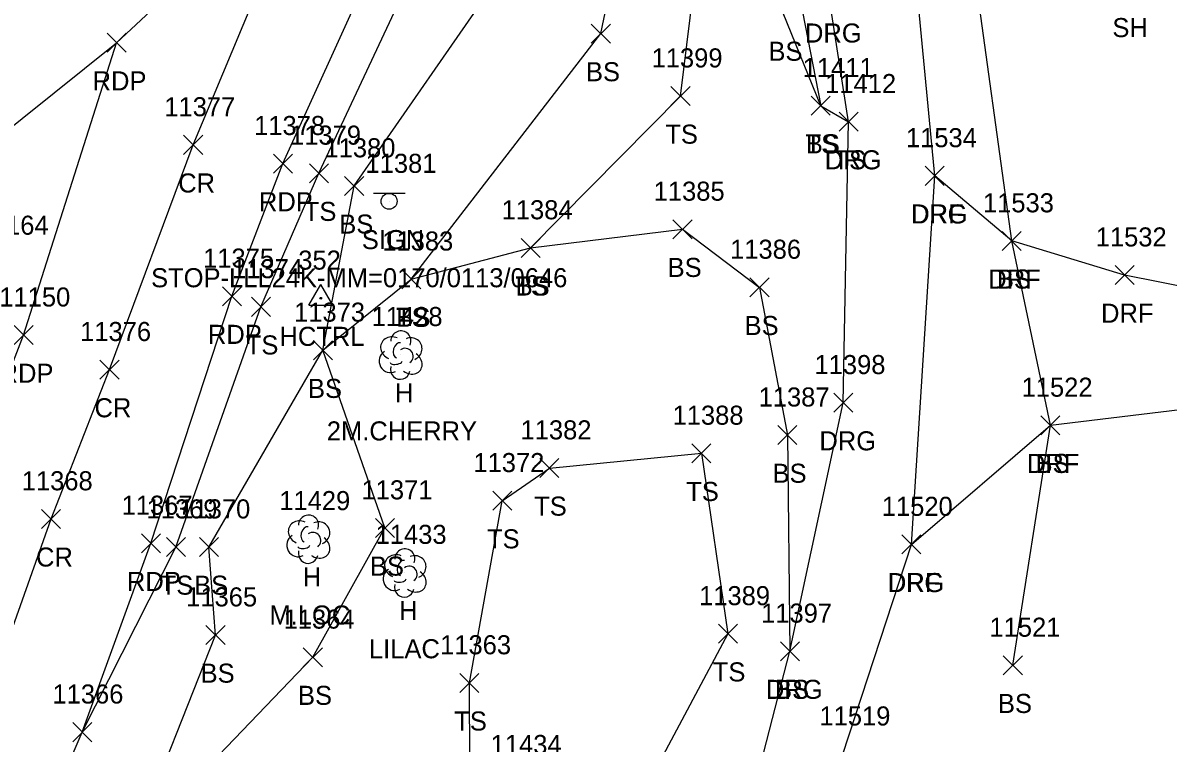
# Model space of a CAD drawing. Extents: x 1475671 to 1477951, y 592661 to 593821.
# Drawn here: x 1476858.4 to 1476978.4, y 593260.4 to 593335.9 of the extents above; entities that cross this region are included whole.
import ezdxf

# ---------------------------------------------------------------- set-up
doc = ezdxf.new("R2010")
doc.units = 0
for name, color, linetype in [('C_A', 7, 'Continuous'), ('C_I', 7, 'Continuous'), ('CPH', 7, 'Continuous'), ('L_A', 7, 'Continuous'), ('L_C', 7, 'Continuous'), ('L_I', 7, 'Continuous'), ('L_TIC', 7, 'Continuous'), ('LELB', 7, 'Continuous'), ('LTD', 7, 'Continuous'), ('P_A', 7, 'Continuous'), ('P_I', 7, 'Continuous'), ('P_TIC', 7, 'Continuous'), ('PET', 7, 'Continuous'), ('PRC', 7, 'Continuous'), ('R_A', 7, 'Continuous'), ('R_I', 7, 'Continuous'), ('R_TIC', 7, 'Continuous'), ('RDF', 7, 'Continuous'), ('RDG', 7, 'Continuous'), ('S_A', 7, 'Continuous'), ('S_C', 7, 'Continuous'), ('S_I', 7, 'Continuous'), ('SSGN', 7, 'Continuous')]:
    doc.layers.add(name, color=color, linetype=linetype)

msp = doc.modelspace()

# ---------------------------------------------------------------- linework, layer by layer
at = {"layer": 'CPH'}
for p, q in [((1476888.35, 593306.34), (1476889.6, 593308.51)), ((1476890.85, 593306.34), (1476889.6, 593308.51)), ((1476888.35, 593306.34), (1476890.85, 593306.34)), ((1476889.6, 593307.06), (1476889.6, 593307.06))]:
    msp.add_line(p, q, dxfattribs=at)
msp.add_circle((1476889.6, 593307.06), 0.0833, dxfattribs=at)
at = {"layer": 'L_TIC'}
for points in [[(1476917.96, 593333.82), (1476919.96, 593335.82)], [(1476919.96, 593333.82), (1476917.96, 593335.82)], [(1476926.31, 593327.27), (1476928.31, 593329.27)], [(1476928.31, 593327.27), (1476926.31, 593329.27)], [(1476941.01, 593326.25), (1476943.01, 593328.25)], [(1476943.01, 593326.25), (1476941.01, 593328.25)], [(1476941.01, 593326.25), (1476943.01, 593328.25)], [(1476943.01, 593326.25), (1476941.01, 593328.25)], [(1476943.94, 593324.58), (1476945.94, 593326.58)], [(1476945.94, 593324.58), (1476943.94, 593326.58)], [(1476888.41, 593319.17), (1476890.41, 593321.17)], [(1476890.41, 593319.17), (1476888.41, 593321.17)], [(1476892.1, 593317.84), (1476894.1, 593319.84)], [(1476894.1, 593317.84), (1476892.1, 593319.84)], [(1476926.52, 593313.29), (1476928.52, 593315.29)], [(1476928.52, 593313.29), (1476926.52, 593315.29)], [(1476961.04, 593312.07), (1476963.04, 593314.07)], [(1476963.04, 593312.07), (1476961.04, 593314.07)], [(1476910.59, 593311.34), (1476912.59, 593313.34)], [(1476912.59, 593311.34), (1476910.59, 593313.34)], [(1476910.59, 593311.34), (1476912.59, 593313.34)], [(1476912.59, 593311.34), (1476910.59, 593313.34)], [(1476898.08, 593308.06), (1476900.08, 593310.06)], [(1476900.08, 593308.06), (1476898.08, 593310.06)], [(1476898.08, 593308.06), (1476900.08, 593310.06)], [(1476900.08, 593308.06), (1476898.08, 593310.06)], [(1476934.59, 593307.2), (1476936.59, 593309.2)], [(1476936.59, 593307.2), (1476934.59, 593309.2)], [(1476882.33, 593305.16), (1476884.33, 593307.16)], [(1476884.33, 593305.16), (1476882.33, 593307.16)], [(1476888.82, 593300.6), (1476890.82, 593302.6)], [(1476890.82, 593300.6), (1476888.82, 593302.6)], [(1476888.82, 593300.6), (1476890.82, 593302.6)], [(1476890.82, 593300.6), (1476888.82, 593302.6)], [(1476965.09, 593292.73), (1476967.09, 593294.73)], [(1476967.09, 593292.73), (1476965.09, 593294.73)], [(1476937.52, 593291.7), (1476939.52, 593293.7)], [(1476939.52, 593291.7), (1476937.52, 593293.7)], [(1476928.5, 593289.79), (1476930.5, 593291.79)], [(1476930.5, 593289.79), (1476928.5, 593291.79)], [(1476912.56, 593288.25), (1476914.56, 593290.25)], [(1476914.56, 593288.25), (1476912.56, 593290.25)], [(1476912.56, 593288.25), (1476914.56, 593290.25)], [(1476914.56, 593288.25), (1476912.56, 593290.25)], [(1476907.62, 593284.82), (1476909.62, 593286.82)], [(1476909.62, 593284.82), (1476907.62, 593286.82)], [(1476895.32, 593281.96), (1476897.32, 593283.96)], [(1476897.32, 593281.96), (1476895.32, 593283.96)], [(1476873.41, 593279.96), (1476875.41, 593281.96)], [(1476875.41, 593279.96), (1476873.41, 593281.96)], [(1476876.88, 593279.96), (1476878.88, 593281.96)], [(1476878.88, 593279.96), (1476876.88, 593281.96)], [(1476877.56, 593270.73), (1476879.56, 593272.73)], [(1476879.56, 593270.73), (1476877.56, 593272.73)], [(1476931.29, 593270.86), (1476933.29, 593272.86)], [(1476933.29, 593270.86), (1476931.29, 593272.86)], [(1476887.77, 593268.4), (1476889.77, 593270.4)], [(1476889.77, 593268.4), (1476887.77, 593270.4)], [(1476937.78, 593269.03), (1476939.78, 593271.03)], [(1476939.78, 593269.03), (1476937.78, 593271.03)], [(1476961.15, 593267.55), (1476963.15, 593269.55)], [(1476963.15, 593267.55), (1476961.15, 593269.55)], [(1476904.18, 593265.71), (1476906.18, 593267.71)], [(1476906.18, 593265.71), (1476904.18, 593267.71)], [(1476863.6, 593260.54), (1476865.6, 593262.54)], [(1476865.6, 593260.54), (1476863.6, 593262.54)]]:
    msp.add_lwpolyline(points, dxfattribs=at)
at = {"layer": 'LELB'}
for points in [[(1476962.15, 593268.55), (1476966.09, 593293.73), (1476962.04, 593313.07), (1476957.94, 593342.76), (1476956.85, 593364.92), (1476946.71, 593381.5), (1476947.26, 593385.01), (1476945.57, 593387.27), (1476956.77, 593393.64), (1476963.43, 593396.59), (1476970.91, 593403.07), (1476974.88, 593411.06), (1477002.6, 593437.22), (1477013.99, 593445.85), (1477022.63, 593453.15), (1477030.46, 593458.56)], [(1476864.6, 593261.54), (1476874.41, 593280.96), (1476883.33, 593306.16), (1476889.41, 593320.17), (1476901.29, 593345.55), (1476912.71, 593361.1), (1476913.88, 593366.51), (1476917.83, 593370.13), (1476924.18, 593369.9), (1476931.14, 593361.7), (1476938.47, 593345.55), (1476942.01, 593327.25), (1476944.94, 593325.58)], [(1476844.89, 593161.77), (1476849.57, 593180.8), (1476849.13, 593190.54), (1476855.62, 593209.87), (1476862.35, 593222.47), (1476869.87, 593249.68), (1476878.56, 593271.73), (1476877.88, 593280.96), (1476889.82, 593301.6), (1476893.1, 593318.84), (1476908.59, 593341.2), (1476918.55, 593355.38), (1476919.84, 593361.76), (1476917.93, 593365.87), (1476921.61, 593367.66), (1476922.08, 593366.69), (1476922.63, 593360.35), (1476925.59, 593366.62)], [(1476899.08, 593309.06), (1476911.59, 593312.34), (1476927.31, 593328.27), (1476930.66, 593355.51), (1476925.59, 593366.62)], [(1476882.63, 593203.65), (1476875.74, 593222.23), (1476869.87, 593249.68), (1476888.77, 593269.4), (1476896.32, 593282.96), (1476889.82, 593301.6), (1476899.08, 593309.06), (1476918.96, 593334.82), (1476923.19, 593355.07), (1476922.63, 593360.35)], [(1476942.01, 593327.25), (1476938.09, 593336.97), (1476930.66, 593355.51)], [(1476911.59, 593312.34), (1476927.52, 593314.29), (1476935.59, 593308.2), (1476938.52, 593292.7), (1476938.78, 593270.03)], [(1476913.56, 593289.25), (1476929.5, 593290.79), (1476932.29, 593271.86), (1476922.08, 593252.68), (1476914.39, 593239.23), (1476908.84, 593217.58), (1476908.1, 593203.87)], [(1476898.32, 593201.52), (1476892.94, 593222.33), (1476905.3, 593240.8), (1476905.18, 593266.71), (1476908.62, 593285.82), (1476913.56, 593289.25)]]:
    msp.add_lwpolyline(points, dxfattribs=at)
at = {"layer": 'LTD'}
for p, q in [((1476897.95, 593301.14), (1476897.95, 593301.14)), ((1476897.95, 593301.14), (1476897.95, 593301.14)), ((1476888.28, 593281.83), (1476888.28, 593281.83)), ((1476888.28, 593281.83), (1476888.28, 593281.83)), ((1476898.37, 593278.29), (1476898.37, 593278.29)), ((1476898.37, 593278.29), (1476898.37, 593278.29))]:
    msp.add_line(p, q, dxfattribs=at)
for centre in [(1476898, 593302.58), (1476888.32, 593283.26), (1476898.42, 593279.72)]:
    msp.add_arc(centre, 1.05, 335.5272, 180.9563, dxfattribs=at)
for centre, major_axis, ratio, start_param, end_param in [((1476897.16, 593301.81), (1.21, -0.51), 0.895232, 1.570796, 4.712389), ((1476898.99, 593301.73), (-1.14, -0.48), 0.949671, 1.570796, 4.712389), ((1476896.87, 593300.43), (0.58, -1.04), 0.959034, 3.141593, 6.283185), ((1476897.74, 593301.6), (-0.208, -0.792), 0.645439, 3.141593, 6.283185), ((1476898.45, 593300.98), (-0.5, 0.667), 0.989748, 3.141593, 6.283185), ((1476897.49, 593300.39), (-0.625, -0.083), 0.423636, 0, 3.141593), ((1476898.95, 593300.31), (-1.09, 0.79), 0.841452, 1.570796, 4.712389), ((1476897.95, 593299.64), (0.26, 1.06), 0.942809, 1.570796, 4.712389), ((1476887.49, 593282.5), (1.21, -0.51), 0.895232, 1.570796, 4.712389), ((1476889.32, 593282.41), (-1.14, -0.48), 0.949671, 1.570796, 4.712389), ((1476888.07, 593282.29), (-0.208, -0.792), 0.645439, 3.141593, 6.283185), ((1476888.78, 593281.66), (-0.5, 0.667), 0.989748, 3.141593, 6.283185), ((1476887.19, 593281.12), (0.58, -1.04), 0.959034, 3.141593, 6.283185), ((1476887.82, 593281.08), (-0.625, -0.083), 0.423636, 0, 3.141593), ((1476889.28, 593281), (-1.09, 0.79), 0.841452, 1.570796, 4.712389), ((1476888.28, 593280.33), (0.26, 1.06), 0.942809, 1.570796, 4.712389), ((1476897.58, 593278.95), (1.21, -0.51), 0.895232, 1.570796, 4.712389), ((1476899.41, 593278.87), (-1.14, -0.48), 0.949671, 1.570796, 4.712389), ((1476898.16, 593278.75), (-0.208, -0.792), 0.645439, 3.141593, 6.283185), ((1476898.87, 593278.12), (-0.5, 0.667), 0.989748, 3.141593, 6.283185), ((1476897.29, 593277.58), (0.58, -1.04), 0.959034, 3.141593, 6.283185), ((1476897.92, 593277.54), (-0.625, -0.083), 0.423636, 0, 3.141593), ((1476899.37, 593277.45), (-1.09, 0.79), 0.841452, 1.570796, 4.712389), ((1476898.37, 593276.79), (0.26, 1.06), 0.942809, 1.570796, 4.712389)]:
    msp.add_ellipse(centre, major_axis=major_axis, ratio=ratio, start_param=start_param, end_param=end_param, dxfattribs=at)
at = {"layer": 'P_TIC'}
for points in [[(1476867.19, 593332.86), (1476869.19, 593334.86)], [(1476869.19, 593332.86), (1476867.19, 593334.86)], [(1476867.19, 593332.86), (1476869.19, 593334.86)], [(1476869.19, 593332.86), (1476867.19, 593334.86)], [(1476875.22, 593322.15), (1476877.22, 593324.15)], [(1476877.22, 593322.15), (1476875.22, 593324.15)], [(1476884.63, 593320.18), (1476886.63, 593322.18)], [(1476886.63, 593320.18), (1476884.63, 593322.18)], [(1476879.28, 593306.27), (1476881.28, 593308.27)], [(1476881.28, 593306.27), (1476879.28, 593308.27)], [(1476857.44, 593302.19), (1476859.44, 593304.19)], [(1476859.44, 593302.19), (1476857.44, 593304.19)], [(1476866.45, 593298.57), (1476868.45, 593300.57)], [(1476868.45, 593298.57), (1476866.45, 593300.57)], [(1476860.32, 593282.91), (1476862.32, 593284.91)], [(1476862.32, 593282.91), (1476860.32, 593284.91)], [(1476870.79, 593280.35), (1476872.79, 593282.35)], [(1476872.79, 593280.35), (1476870.79, 593282.35)], [(1476863.6, 593260.54), (1476865.6, 593262.54)], [(1476865.6, 593260.54), (1476863.6, 593262.54)]]:
    msp.add_lwpolyline(points, dxfattribs=at)
at = {"layer": 'PET'}
for points in [[(1476493.61, 593061.9), (1476518.9, 593073.26), (1476550.12, 593088.22), (1476579.1, 593105.35), (1476612.57, 593127.79), (1476627.64, 593138.01), (1476653.65, 593155.86), (1476677.37, 593174.62), (1476705.43, 593196.67), (1476722.66, 593210.69), (1476749.61, 593233.45), (1476768.81, 593249.96), (1476797.5, 593274.02), (1476824.82, 593297.55), (1476845, 593315.29), (1476868.19, 593333.86), (1476888.66, 593352.98), (1476918.01, 593376.95), (1476944.23, 593398.87), (1476967.73, 593418.7), (1476998.53, 593444.47)], [(1476852.05, 593085.53), (1476845.73, 593108.15), (1476841.01, 593134.78), (1476840.06, 593162.08), (1476843.4, 593187.72), (1476850.39, 593217.62), (1476860.98, 593253.11), (1476864.6, 593261.54), (1476871.79, 593281.35), (1476880.28, 593307.27), (1476885.63, 593321.18), (1476897.83, 593348.03), (1476918.01, 593376.95)], [(1476550.12, 593088.22), (1476546.99, 593080.79), (1476546.62, 593074.3), (1476558.02, 593070.45), (1476566.6, 593070.83), (1476605.7, 593074.02), (1476651.65, 593078.89), (1476683.81, 593086.28), (1476716.78, 593091.72), (1476756.3, 593096.32), (1476786.76, 593094.61), (1476795.52, 593092.66), (1476816.88, 593085.29), (1476835.43, 593074.22), (1476828.62, 593102.02), (1476824.42, 593119.75), (1476821.59, 593140.77), (1476821.02, 593163.56), (1476821.92, 593180.44), (1476827.12, 593207.84), (1476837.47, 593243.39), (1476848.83, 593278.3), (1476858.44, 593303.19), (1476868.19, 593333.86)]]:
    msp.add_lwpolyline(points, dxfattribs=at)
at = {"layer": 'PRC'}
msp.add_lwpolyline([(1476853.41, 593046.52), (1476841.6, 593084.28), (1476835.78, 593107.15), (1476831.7, 593132.51), (1476830.84, 593162.78), (1476833.45, 593190.92), (1476841.31, 593223.69), (1476851.49, 593256.16), (1476861.32, 593283.91), (1476867.45, 593299.57), (1476876.22, 593323.15), (1476888.66, 593352.98)], dxfattribs=at)
at = {"layer": 'R_TIC'}
for points in [[(1476943.94, 593324.58), (1476945.94, 593326.58)], [(1476945.94, 593324.58), (1476943.94, 593326.58)], [(1476952.96, 593318.9), (1476954.96, 593320.9)], [(1476954.96, 593318.9), (1476952.96, 593320.9)], [(1476952.96, 593318.9), (1476954.96, 593320.9)], [(1476954.96, 593318.9), (1476952.96, 593320.9)], [(1476961.04, 593312.07), (1476963.04, 593314.07)], [(1476963.04, 593312.07), (1476961.04, 593314.07)], [(1476972.87, 593308.49), (1476974.87, 593310.49)], [(1476974.87, 593308.49), (1476972.87, 593310.49)], [(1476943.38, 593295.1), (1476945.38, 593297.1)], [(1476945.38, 593295.1), (1476943.38, 593297.1)], [(1476965.09, 593292.73), (1476967.09, 593294.73)], [(1476967.09, 593292.73), (1476965.09, 593294.73)], [(1476950.52, 593280.23), (1476952.52, 593282.23)], [(1476952.52, 593280.23), (1476950.52, 593282.23)], [(1476950.52, 593280.23), (1476952.52, 593282.23)], [(1476952.52, 593280.23), (1476950.52, 593282.23)], [(1476937.78, 593269.03), (1476939.78, 593271.03)], [(1476939.78, 593269.03), (1476937.78, 593271.03)]]:
    msp.add_lwpolyline(points, dxfattribs=at)
at = {"layer": 'RDF'}
for points in [[(1477025, 593308.34), (1477007.8, 593304.64), (1476992.38, 593305.8), (1476973.87, 593309.49), (1476962.04, 593313.07), (1476953.96, 593319.9)], [(1476951.52, 593281.23), (1476966.09, 593293.73), (1476987.21, 593296.29), (1477002.39, 593292.57), (1477022.95, 593291.85)]]:
    msp.add_lwpolyline(points, dxfattribs=at)
at = {"layer": 'RDG'}
for points in [[(1476954.02, 593202.34), (1476939.16, 593211.9), (1476944.34, 593259.24), (1476951.52, 593281.23), (1476953.96, 593319.9), (1476951.87, 593341.86), (1476947.54, 593363.24), (1476941.61, 593379.55), (1476939.44, 593381.51), (1476939.12, 593387.06), (1476944.23, 593398.87)], [(1476850.39, 593217.62), (1476855.62, 593209.87), (1476871.37, 593205.7), (1476882.63, 593203.65), (1476898.32, 593201.52), (1476908.1, 593203.87), (1476921.63, 593214.39), (1476929.61, 593231.45), (1476934.18, 593252.23), (1476938.78, 593270.03), (1476944.38, 593296.1), (1476944.94, 593325.58), (1476942.87, 593338.88), (1476933.5, 593367.74), (1476927.3, 593373.86), (1476918.01, 593376.95)]]:
    msp.add_lwpolyline(points, dxfattribs=at)
at = {"layer": 'SSGN'}
for p, q in [((1476895.11, 593318.07), (1476898.45, 593318.07)), ((1476896.76, 593317.23), (1476896.76, 593317.23))]:
    msp.add_line(p, q, dxfattribs=at)
msp.add_circle((1476896.76, 593317.23), 0.833, dxfattribs=at)

# ---------------------------------------------------------------- texts
at = {"layer": 'C_A'}
msp.add_text('HCTRL', height=2, dxfattribs=at).set_placement((1476885.27, 593302.06))
at = {"layer": 'C_I'}
msp.add_text('352', height=2, dxfattribs=at).set_placement((1476887.24, 593310.06))
at = {"layer": 'L_A'}
for s, p in [('SH', (1476972.59, 593334.45)), ('BS', (1476936.53, 593331.97)), ('BS', (1476917.4, 593329.82)), ('TS', (1476925.72, 593323.27)), ('TS', (1476940.42, 593322.25)), ('BS', (1476940.45, 593322.25)), ('TS', (1476943.35, 593320.58)), ('TS', (1476887.82, 593315.17)), ('BS', (1476891.54, 593313.84)), ('BS', (1476925.96, 593309.29)), ('BS', (1476960.48, 593308.07)), ('TS', (1476909.99, 593307.34)), ('BS', (1476910.03, 593307.34)), ('TS', (1476897.49, 593304.06)), ('BS', (1476897.52, 593304.06)), ('BS', (1476934.03, 593303.2)), ('TS', (1476881.74, 593301.16)), ('BS', (1476888.26, 593296.6)), ('BS', (1476888.26, 593296.6)), ('H', (1476897.38, 593296.14)), ('BS', (1476964.53, 593288.73)), ('BS', (1476936.96, 593287.7)), ('TS', (1476927.91, 593285.79)), ('TS', (1476911.97, 593284.25)), ('TS', (1476911.97, 593284.25)), ('TS', (1476907.03, 593280.82)), ('BS', (1476894.76, 593277.96)), ('H', (1476887.71, 593276.83)), ('TS', (1476872.82, 593275.96)), ('BS', (1476876.32, 593275.96)), ('H', (1476897.81, 593273.29)), ('BS', (1476877, 593266.73)), ('TS', (1476930.7, 593266.86)), ('BS', (1476937.22, 593265.03)), ('BS', (1476887.21, 593264.4)), ('BS', (1476960.59, 593263.55)), ('TS', (1476903.59, 593261.71))]:
    msp.add_text(s, height=2, dxfattribs=at).set_placement(p)
at = {"layer": 'L_C'}
for s, p in [('2M.CHERRY', (1476890.23, 593292.14)), ('M.LOC', (1476884.22, 593272.83)), ('LILAC', (1476894.65, 593269.29))]:
    msp.add_text(s, height=2, dxfattribs=at).set_placement(p)
at = {"layer": 'L_I'}
for s, p in [('11399', (1476924.28, 593331.27)), ('11411', (1476940.12, 593330.25)), ('11411', (1476940.12, 593330.25)), ('11412', (1476942.48, 593328.58)), ('11379', (1476886.38, 593323.17)), ('11380', (1476889.99, 593321.84)), ('11385', (1476924.5, 593317.29)), ('11384', (1476908.56, 593315.34)), ('11384', (1476908.56, 593315.34)), ('11533', (1476959.02, 593316.07)), ('11164', (1476853.63, 593313.72)), ('11164', (1476853.63, 593313.72)), ('11383', (1476896.05, 593312.06)), ('11383', (1476896.05, 593312.06)), ('11386', (1476932.51, 593311.2)), ('11374', (1476880.3, 593309.16)), ('11373', (1476886.8, 593304.6)), ('11373', (1476886.8, 593304.6)), ('11428', (1476894.93, 593304.14)), ('11522', (1476963.07, 593296.73)), ('11387', (1476935.5, 593295.7)), ('11388', (1476926.48, 593293.79)), ('11382', (1476910.54, 593292.25)), ('11382', (1476910.54, 593292.25)), ('11372', (1476905.6, 593288.82)), ('11371', (1476893.87, 593285.96)), ('11369', (1476871.33, 593283.96)), ('11370', (1476874.77, 593283.96)), ('11429', (1476885.25, 593284.83)), ('11433', (1476895.35, 593281.29)), ('11365', (1476875.49, 593274.73)), ('11389', (1476929.26, 593274.86)), ('11397', (1476935.76, 593273.03)), ('11364', (1476885.7, 593272.4)), ('11521', (1476959.7, 593271.55)), ('11363', (1476902.11, 593269.71)), ('11366', (1476861.47, 593264.54)), ('11434', (1476907.41, 593259.25))]:
    msp.add_text(s, height=2, dxfattribs=at).set_placement(p)
at = {"layer": 'P_A'}
for s, p in [('RDP', (1476865.68, 593328.86)), ('RDP', (1476865.68, 593328.86)), ('CR', (1476874.65, 593318.15)), ('RDP', (1476883.12, 593316.18)), ('RDP', (1476877.77, 593302.27)), ('RDP', (1476855.93, 593298.19)), ('CR', (1476865.88, 593294.57)), ('CR', (1476859.75, 593278.91)), ('RDP', (1476869.28, 593276.35))]:
    msp.add_text(s, height=2, dxfattribs=at).set_placement(p)
at = {"layer": 'P_I'}
for s, p in [('11377', (1476873.2, 593326.15)), ('11378', (1476882.61, 593324.18)), ('11375', (1476877.26, 593310.27)), ('11150', (1476855.9, 593306.19)), ('11376', (1476864.37, 593302.57)), ('11368', (1476858.25, 593286.91)), ('11367', (1476868.72, 593284.35)), ('11366', (1476861.47, 593264.54))]:
    msp.add_text(s, height=2, dxfattribs=at).set_placement(p)
at = {"layer": 'R_A'}
for s, p in [('DRG', (1476940.36, 593333.88)), ('DRG', (1476942.43, 593320.58)), ('DRG', (1476951.45, 593314.9)), ('DRF', (1476951.5, 593314.9)), ('DRF', (1476959.58, 593308.07)), ('DRF', (1476971.4, 593304.49)), ('DRG', (1476941.87, 593291.1)), ('DRF', (1476963.63, 593288.73)), ('DRG', (1476949.01, 593276.23)), ('DRF', (1476949.06, 593276.23)), ('DRG', (1476936.27, 593265.03))]:
    msp.add_text(s, height=2, dxfattribs=at).set_placement(p)
at = {"layer": 'R_I'}
for s, p in [('11412', (1476942.48, 593328.58)), ('11534', (1476950.94, 593322.9)), ('11534', (1476950.94, 593322.9)), ('11533', (1476959.02, 593316.07)), ('11532', (1476970.84, 593312.49)), ('11398', (1476941.36, 593299.1)), ('11522', (1476963.07, 593296.73)), ('11520', (1476948.41, 593284.23)), ('11520', (1476948.41, 593284.23)), ('11397', (1476935.76, 593273.03)), ('11519', (1476941.88, 593262.24))]:
    msp.add_text(s, height=2, dxfattribs=at).set_placement(p)
at = {"layer": 'S_A'}
msp.add_text('SIGN', height=2, dxfattribs=at).set_placement((1476893.9, 593312.21))
at = {"layer": 'S_C'}
msp.add_text('STOP-LLL24K-MM=0170/0113/0646', height=2, dxfattribs=at).set_placement((1476871.81, 593308.21))
at = {"layer": 'S_I'}
msp.add_text('11381', height=2, dxfattribs=at).set_placement((1476894.29, 593320.21))

doc.saveas('drawing.dxf')
